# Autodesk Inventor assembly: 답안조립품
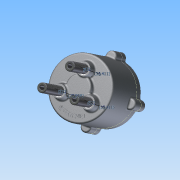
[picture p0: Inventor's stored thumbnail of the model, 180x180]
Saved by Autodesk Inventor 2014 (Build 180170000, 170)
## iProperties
Created: 2015-09
Part Number: 답안조립품
Document SubType Name: Assembly
Designer: study
Mass: 2160.14 g
Surface Area: 1801.25 cm^2
Volume: 438.509 cm^3
Density: 4.92611 g/cm^3
Author: study
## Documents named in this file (14)
- C:\Users\study\Desktop\350916V1003\답안조립품.iam
- C:\Users\study\Desktop\350916V1003\몸체.ipt
- C:\Users\study\Desktop\350916V1003\베어링 NA 4900.ipt
- C:\Users\study\Desktop\350916V1003\오일실.ipt
- C:\Users\study\Desktop\350916V1003\커버.ipt
- C:\Users\study\Desktop\350916V1003\메인 축.ipt
- C:\Users\study\Desktop\350916V1003\멈춤링 10 x 1.ipt
- C:\Users\study\Desktop\350916V1003\멈춤링 22 x 1.2.ipt
- C:\Users\study\Desktop\350916V1003\슬라이드 축.ipt
- C:\Users\study\Desktop\350916V1003\판캠.ipt
- C:\Users\study\Desktop\350916V1003\M5x0.8x20.ipt
- C:\Users\study\Desktop\350916V1003\가변스프링2.ipt
- C:\Users\study\Desktop\350916V1003\가변스프링3.ipt
- C:\Users\study\Desktop\350916V1003\가변스프링1.ipt
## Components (7 placed, 4 different names)
1. 가변스프링2:1
2. 가변스프링3:1
3. 가변스프링1:1
4. M5x0.8x20:1
5. M5x0.8x20:2
6. M5x0.8x20:3
7. M5x0.8x20:4
